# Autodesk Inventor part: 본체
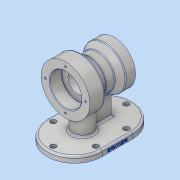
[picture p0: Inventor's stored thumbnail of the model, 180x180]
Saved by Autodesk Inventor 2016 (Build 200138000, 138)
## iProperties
Created: 2020-01
Part Number: 본체
Material: 알루미늄 6061
Document SubType Name: Modeling
Designer: woori
Density: 2.7 g/cm^3
Appearance: 알루미늄 - 평지
Mass: 938.29 g
Surface Area: 656.219 cm^2
Volume: 347.515 cm^3
Author: woori
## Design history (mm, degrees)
sketch "스케치1"
  geometry: L1 (0, 0)-(0, 40); L2 (0, 40)-(24, 40); L3 (24, 40)-(38.897, 27.5); L4 (38.897, 27.5)-(53.289, 27.5); L5 (53.289, 27.5)-(64, 35); L6 (64, 35)-(80, 35); L7 (80, 35)-(80, 0); L8 (0, 0)-(80, 0); L9 (32.583, 27.5)-(57.394, 27.5)
  constraints: 18 end point, 2 horizontal, 2 parallel, 2 perpendicular, 1 horizontal alignment, 1 vertical
  dimensions: "d1" = 24 distance of L1.end L2.end; "d2" = 16 distance of L5.end L6.end; "d3" = 80 distance between parallel lines of L1 L7; "d4" = 80 diameter of L2 L8; "d5" = 55 diameter of L4 L8; "d6" = 70 diameter of L6 L8; "d72" = 40 deg angle of L9 L3; "d73" = 35 deg angle of L5 L9
revolve "회전1" sketch "스케치1" stored, may be unused: angle "d7" = 90 deg
node "작업 평면1"
sketch "스케치2"
  geometry: L1 (40, 0)-(-40, 0) reference; L2 (-45, 15)-(-45, 65); L3 (45, 15)-(45, 65); L4 (45, 15)-(95, 15); A1 r 45 centre (0, 15) between (-45, 15) and (45, 15); A2 r 45 centre (0, 65) between (45, 65) and (-45, 65); 1 further point
  constraints: 6 end point, 4 point on circle, 2 centre point, 2 vertical, 1 horizontal, 1 perpendicular, 1 tangent
  dimensions: "d10" = 90 diameter of A1; "d13" = 30 distance edge to line of A1 L1; "d14" = 50 distance of L2.end L2.start; "d15" = 50 distance of L3.end L3.start; "d16" = 90 deg angle of L4 L3 (derived)
extrude "돌출1" join sketch "스케치2" distance "d17" = 10; taper "d18" = 0 deg
sketch "스케치3"
  geometry: L1 (35, 80)-(-35, 80) reference; L2 (-5, 70)-(5, 70); L3 (5, 70)-(5, 43.199); L4 (-5, 43.199)-(-5, 70); L5 (0, -30)-(26.772, -30); A1 r 16 centre (0, 28) between (-5, 43.199) and (5, 43.199); A2 r 45 centre (0, 15) between (-45, 15) and (45, 15) reference; 2 further points
  constraints: 8 end point, 3 point on circle, 2 horizontal, 1 centre point, 1 parallel, 1 perpendicular, 1 tangent, 1 vertical alignment
  dimensions: "d19" = 10 distance between parallel lines of L1 L2; "d20" = 10 distance of L2.start L2.end; "d22" = 32 diameter of A1; "d23" = 58 distance from line of A1.centre L5
extrude "돌출2" join sketch "스케치3" distance "d24" = 70; taper "d25" = 0 deg
sketch "스케치5" dims "d36" = 66
  geometry: 3 further points
  constraints: 1 coincident, 1 vertical alignment, 2 other
hole "구멍1" sketch "스케치5" at (0, 33) diameter "d37" = 3.242; stored, may be unused: countersink angle "d41" = 90 deg, drill point angle "d43" = 118 deg; dims "d38" = 9, "d39" = 4, "d40" = 2, "d42" = 11
sketch "스케치6" dims "d47" = 55
  geometry: 3 further points
  constraints: 1 coincident, 1 vertical alignment, 2 other
hole "구멍2" sketch "스케치6" at (0, -27.5) diameter "d48" = 3.242; stored, may be unused: countersink angle "d52" = 90 deg, drill point angle "d54" = 118 deg; dims "d49" = 9, "d50" = 4, "d51" = 2, "d53" = 11
sketch "스케치8"
  geometry: L1 (0, -45)-(-10, -45) reference; L2 (0, 95)-(0, 50) reference; 2 further points
  constraints: 1 other
  dimensions: "d68" = 4 distance from line of L2 point (-4, 25); "d69" = 70 distance from line of L1 point (-4, 25)
feature "엠보싱1" sketch "스케치8" dims "d70" = 0.5, "d71" = 0
fillet "모깎기1" dims "d74" = 3
sketch "스케치9"
  geometry: L1 (0, -40)-(0, 40) reference; L2 (0, 26)-(20, 26); L3 (-9.282, 0)-(95.754, 0); L4 (80, -35)-(80, 35) reference; L5 (64, -34.641)-(64, 35) reference; L6 (80, 20)-(63, 20); L7 (20, 16)-(63, 16); L8 (20, 26)-(20, 16); L9 (63, 20)-(63, 16); L10 (80, 20)-(80, 0); L11 (0, 26)-(0, 0); L12 (0, -1.621)-(0, 1.621) reference; L13 (0, 0)-(80, 0); 2 further points
  constraints: 18 end point, 4 horizontal, 3 midpoint, 2 collinear, 2 point on line, 1 horizontal alignment, 1 parallel, 1 vertical
  dimensions: "d75" = 20 distance of L2.start L2.end; "d76" = 52 diameter of L2 L3; "d78" = 17 distance of L6.start L6.end; "d79" = 40 diameter of L6 L3; "d80" = 32 diameter of L7 L3
revolve "회전3" sketch "스케치9" stored, may be unused: angle "d81" = 90 deg
chamfer "모따기1" distance "d82" = 1; stored, may be unused: second distance "d83" = 2, angle "d84" = 45 deg
fillet "모깎기2" dims "d85" = 0.3
fillet "모깎기3" dims "d86" = 3
fillet "모깎기4" dims "d87" = 3
fillet "모깎기5" dims "d88" = 3
sketch "스케치10"
  geometry: L1 (-45, 65)-(-45, 15) reference; L2 (45, 15)-(45, 65) reference; L3 (-35, 15)-(-35, 65); L4 (35, 65)-(35, 15); A1 r 45 centre (0, 15) between (-45, 15) and (45, 15) reference; A2 r 45 centre (0, 65) between (45, 65) and (-45, 65) reference; A3 r 35 centre (0, 15) between (-35, 15) and (35, 15); A4 r 35 centre (0, 65) between (35, 65) and (-35, 65); 7 further points
  constraints: 6 point on circle, 4 end point, 3 coincident, 2 centre point, 1 point on line, 3 other
  dimensions: "d90" = 10 radial gap between concentric circles of A1 A3
hole "구멍4" sketch "스케치10" at (0, -20), (0, 100), (35, 15), (35, 65), (-35, 15), (-35, 65) diameter "d91" = 9; stored, may be unused: countersink angle "d95" = 90 deg, drill point angle "d97" = 0 deg; dims "d92" = 9, "d93" = 4, "d94" = 2, "d96" = 10
node "솔리드1"
pattern_circular "원형 패턴1" dims angle "d45" = 360 deg
pattern_circular "원형 패턴2" dims angle "d56" = 360 deg
